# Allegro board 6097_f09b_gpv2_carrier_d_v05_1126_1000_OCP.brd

Outline 210 x 148 mm; copper layers: TOP, GND, IN1, GND1, VCC, VCC1, GND2, IN2, GND3, BOTTOM. Coordinates in mm from the lower left corner of the outline.
Outline path: 0,121.5 0,2 arc(0.59,0.59) 2,0 208,0 arc(209.41,0.59) 210,2 210,121.5 arc(209.41,122.91) 208,123.5 195.5,123.5 arc(194.09,124.09) 193.5,125.5 193.5,146 arc(192.91,147.41) 191.5,148 119.8,148 119.8,146.42 arc(119.38,146) 118.95,146.42 118.95,148 115.05,148 115.05,146.42 arc(114.63,146.01) 114.21,146.42 114.21,148 18.5,148 arc(17.09,147.41) 16.5,146 16.5,125.5 arc(15.91,124.09) 14.5,123.5 2,123.5 arc(0.59,122.91) 0,121.5 ; 27.08,20.8 arc(28.68,22.4) 30.28,20.8 30.28,19.2 arc(28.68,17.6) 27.08,19.2 27.08,20.8 ; 36.83,28.05 arc(38.43,29.65) 40.03,28.05 40.03,26.45 arc(38.43,24.85) 36.83,26.45 36.83,28.05 ; 51.08,20.8 arc(52.68,22.4) 54.28,20.8 54.28,19.2 arc(52.68,17.6) 51.08,19.2 51.08,20.8 ; 60.83,28.05 arc(62.43,29.65) 64.03,28.05 64.03,26.45 arc(62.43,24.85) 60.83,26.45 60.83,28.05 ; 75.08,20.8 arc(76.68,22.4) 78.28,20.8 78.28,19.2 arc(76.68,17.6) 75.08,19.2 75.08,20.8 ; 84.83,28.05 arc(86.43,29.65) 88.03,28.05 88.03,26.45 arc(86.43,24.85) 84.83,26.45 84.83,28.05 ; 99.08,20.8 arc(100.68,22.4) 102.28,20.8 102.28,19.2 arc(100.68,17.6) 99.08,19.2 99.08,20.8 ; 108.83,28.05 arc(110.43,29.65) 112.03,28.05 112.03,26.45 arc(110.43,24.85) 108.83,26.45 108.83,28.05 ; 112.49,146.88 arc(112.91,147.3) 113.33,146.88 113.33,146.22 arc(112.91,145.8) 112.49,146.22 112.49,146.88 ; 114.45,143.65 arc(114.78,143.98) 115.11,143.65 115.11,143.45 arc(114.78,143.12) 114.45,143.45 114.45,143.65 ; 118.9,143.65 arc(119.23,143.98) 119.56,143.65 119.56,143.45 arc(119.23,143.12) 118.9,143.45 118.9,143.65 ; 120.67,146.88 arc(121.09,147.3) 121.51,146.88 121.51,146.22 arc(121.09,145.8) 120.67,146.22 120.67,146.88 ; 123.08,20.8 arc(124.68,22.4) 126.28,20.8 126.28,19.2 arc(124.68,17.6) 123.08,19.2 123.08,20.8 ; 132.83,28.05 arc(134.43,29.65) 136.03,28.05 136.03,26.45 arc(134.43,24.85) 132.83,26.45 132.83,28.05 ; 147.08,20.8 arc(148.68,22.4) 150.28,20.8 150.28,19.2 arc(148.68,17.6) 147.08,19.2 147.08,20.8 ; 156.83,28.05 arc(158.43,29.65) 160.03,28.05 160.03,26.45 arc(158.43,24.85) 156.83,26.45 156.83,28.05

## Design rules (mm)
net group CLK_25M_MINIBMC_CLKIN_R: nets CLK_25M_MINIBMC_CLKIN CLK_25M_MINIBMC_CLKIN_R
net group CLK_100M_PESW_S3_DB1200_C_DN: nets CLK_100M_PESW_S3_DB1200_C_DN CLK_100M_PESW_S3_DB1200_DN
net group CLK_100M_PESW_S3_DB1200_C_DP: nets CLK_100M_PESW_S3_DB1200_C_DP CLK_100M_PESW_S3_DB1200_DP
net group CLKBUF_M2A_OE_N: nets CLKBUF_M2A_OE_N CLKBUF_M2A_OE_N_R
net group CLKBUF_M2B_OE_N: nets CLKBUF_M2B_OE_N CLKBUF_M2B_OE_N_R
net group CLKBUF_M2C_OE_N: nets CLKBUF_M2C_OE_N CLKBUF_M2C_OE_N_R
net group CLKBUF_M2D_OE_N: nets CLKBUF_M2D_OE_N CLKBUF_M2D_OE_N_R
net group CLKBUF_M2E_OE_N: nets CLKBUF_M2E_OE_N CLKBUF_M2E_OE_N_R
net group CLKBUF_M2F_OE_N: nets CLKBUF_M2F_OE_N CLKBUF_M2F_OE_N_R
net group CLKBUF_M2G_OE_N: nets CLKBUF_M2G_OE_N CLKBUF_M2G_OE_N_R
net group CLKBUF_M2H_OE_N: nets CLKBUF_M2H_OE_N CLKBUF_M2H_OE_N_R
net group CLKBUF_M2I_OE_N: nets CLKBUF_M2I_OE_N CLKBUF_M2I_OE_N_R
net group CLKBUF_M2J_OE_N: nets CLKBUF_M2J_OE_N CLKBUF_M2J_OE_N_R
net group CLKBUF_M2K_OE_N: nets CLKBUF_M2K_OE_N CLKBUF_M2K_OE_N_R
net group CLKBUF_M2L_OE_N: nets CLKBUF_M2L_OE_N CLKBUF_M2L_OE_N_R
net group COM_GP_TX: nets COM_GP_TX COM_GP_TX_R
net group FM_BIC_DEBUG_EN: nets FM_BIC_DEBUG_EN FM_BIC_DEBUG_EN_R
net group FM_BIC_M2A_EN: nets FM_BIC_M2A_EN FM_BIC_M2A_EN_R
net group FM_BIC_M2B_EN: nets FM_BIC_M2B_EN FM_BIC_M2B_EN_R
net group FM_BIC_M2C_EN: nets FM_BIC_M2C_EN FM_BIC_M2C_EN_R
net group FM_BIC_M2D_EN: nets FM_BIC_M2D_EN FM_BIC_M2D_EN_R
net group FM_BIC_M2E_EN: nets FM_BIC_M2E_EN FM_BIC_M2E_EN_R
net group FM_BIC_M2F_EN: nets FM_BIC_M2F_EN FM_BIC_M2F_EN_R
net group FM_BIC_M2G_EN: nets FM_BIC_M2G_EN FM_BIC_M2G_EN_R
net group FM_BIC_M2H_EN: nets FM_BIC_M2H_EN FM_BIC_M2H_EN_R
net group FM_BIC_M2I_EN: nets FM_BIC_M2I_EN FM_BIC_M2I_EN_R
net group FM_BIC_M2J_EN: nets FM_BIC_M2J_EN FM_BIC_M2J_EN_R
net group FM_BIC_M2K_EN: nets FM_BIC_M2K_EN FM_BIC_M2K_EN_R
net group FM_BIC_M2L_EN: nets FM_BIC_M2L_EN FM_BIC_M2L_EN_R
net group FM_CLKBUF_DB1200_EN_R: nets FM_CLKBUF_DB1200_EN FM_CLKBUF_DB1200_EN_R
net group FM_COM_EN_N: nets FM_COM_EN_N FM_COM_EN_N_R
net group FM_COM_SEL_0: nets FM_COM_SEL_0 FM_COM_SEL_0_R
net group FM_COM_SEL_1: nets FM_COM_SEL_1 FM_COM_SEL_1_R
net group FM_COM_SEL_2: nets FM_COM_SEL_2 FM_COM_SEL_2_R
net group FM_COM_SEL_3: nets FM_COM_SEL_3 FM_COM_SEL_3_R
net group FM_JTAG_EN_N: nets FM_JTAG_EN_N FM_JTAG_EN_N_R
net group FM_JTAG_SEL_0: nets FM_JTAG_SEL_0 FM_JTAG_SEL_0_R
net group FM_JTAG_SEL_1: nets FM_JTAG_SEL_1 FM_JTAG_SEL_1_R
net group FM_JTAG_SEL_2: nets FM_JTAG_SEL_2 FM_JTAG_SEL_2_R
net group FM_JTAG_SEL_3: nets FM_JTAG_SEL_3 FM_JTAG_SEL_3_R
net group FM_PLD_VCCIO_1_5_P1V8: nets FM_PLD_VCCIO_1_5_P1V8 FM_PLD_VCCIO_1_5_P1V8_R
net group FM_PLD_VCCIO_1_5_P3V3SB: nets FM_PLD_VCCIO_1_5_P3V3SB FM_PLD_VCCIO_1_5_P3V3SB_R
net group I2C_PESW_M2A_EN_LVC: nets I2C_PESW_M2A_EN_LVC I2C_PESW_M2A_EN_LVC_R
net group I2C_PESW_M2A_EN_R: nets I2C_PESW_M2A_EN I2C_PESW_M2A_EN_R
net group I2C_PESW_M2B_EN_LVC: nets I2C_PESW_M2B_EN_LVC I2C_PESW_M2B_EN_LVC_R
net group I2C_PESW_M2B_EN_R: nets I2C_PESW_M2B_EN I2C_PESW_M2B_EN_R
net group I2C_PESW_M2C_EN_LVC: nets I2C_PESW_M2C_EN_LVC I2C_PESW_M2C_EN_LVC_R
net group I2C_PESW_M2C_EN_R: nets I2C_PESW_M2C_EN I2C_PESW_M2C_EN_R
net group I2C_PESW_M2D_EN_LVC: nets I2C_PESW_M2D_EN_LVC I2C_PESW_M2D_EN_LVC_R
net group I2C_PESW_M2D_EN_R: nets I2C_PESW_M2D_EN I2C_PESW_M2D_EN_R
net group I2C_PESW_M2E_EN_LVC: nets I2C_PESW_M2E_EN_LVC I2C_PESW_M2E_EN_LVC_R
net group I2C_PESW_M2E_EN_R: nets I2C_PESW_M2E_EN I2C_PESW_M2E_EN_R
net group I2C_PESW_M2F_EN_LVC: nets I2C_PESW_M2F_EN_LVC I2C_PESW_M2F_EN_LVC_R
net group I2C_PESW_M2F_EN_R: nets I2C_PESW_M2F_EN I2C_PESW_M2F_EN_R
net group I2C_PESW_M2G_EN_LVC: nets I2C_PESW_M2G_EN_LVC I2C_PESW_M2G_EN_LVC_R
net group I2C_PESW_M2G_EN_R: nets I2C_PESW_M2G_EN I2C_PESW_M2G_EN_R
net group I2C_PESW_M2H_EN_LVC: nets I2C_PESW_M2H_EN_LVC I2C_PESW_M2H_EN_LVC_R
net group I2C_PESW_M2H_EN_R: nets I2C_PESW_M2H_EN I2C_PESW_M2H_EN_R
net group I2C_PESW_M2I_EN_LVC: nets I2C_PESW_M2I_EN_LVC I2C_PESW_M2I_EN_LVC_R
net group I2C_PESW_M2I_EN_R: nets I2C_PESW_M2I_EN I2C_PESW_M2I_EN_R
net group I2C_PESW_M2J_EN_LVC: nets I2C_PESW_M2J_EN_LVC I2C_PESW_M2J_EN_LVC_R
net group I2C_PESW_M2J_EN_R: nets I2C_PESW_M2J_EN I2C_PESW_M2J_EN_R
net group I2C_PESW_M2K_EN_LVC: nets I2C_PESW_M2K_EN_LVC I2C_PESW_M2K_EN_LVC_R
net group I2C_PESW_M2K_EN_R: nets I2C_PESW_M2K_EN I2C_PESW_M2K_EN_R
net group I2C_PESW_M2L_EN_LVC: nets I2C_PESW_M2L_EN_LVC I2C_PESW_M2L_EN_LVC_R
net group I2C_PESW_M2L_EN_R: nets I2C_PESW_M2L_EN I2C_PESW_M2L_EN_R
net group I2C_PESW_MULTI_CONFIG_ADD0: nets I2C_PESW_MULTI_CONFIG_ADD0 I2C_PESW_MULTI_CONFIG_ADD0_R
net group I2C_PESW_MULTI_CONFIG_ADD0_L: nets I2C_PESW_MULTI_CONFIG_ADD0_L I2C_PESW_MULTI_CONFIG_ADD0_L_R
net group I2C_PESW_MULTI_CONFIG_ADD1: nets I2C_PESW_MULTI_CONFIG_ADD1 I2C_PESW_MULTI_CONFIG_ADD1_R
net group I2C_PESW_MULTI_CONFIG_ADD1_L: nets I2C_PESW_MULTI_CONFIG_ADD1_L I2C_PESW_MULTI_CONFIG_ADD1_L_R
net group I2C_PESW_MULTI_CONFIG_ADD2: nets I2C_PESW_MULTI_CONFIG_ADD2 I2C_PESW_MULTI_CONFIG_ADD2_R
net group I2C_PESW_MULTI_CONFIG_ADD2_L: nets I2C_PESW_MULTI_CONFIG_ADD2_L I2C_PESW_MULTI_CONFIG_ADD2_L_R
net group I2C_PESW_MULTI_CONFIG_ADD3: nets I2C_PESW_MULTI_CONFIG_ADD3 I2C_PESW_MULTI_CONFIG_ADD3_R
net group I2C_PESW_MULTI_CONFIG_ADD3_L: nets I2C_PESW_MULTI_CONFIG_ADD3_L I2C_PESW_MULTI_CONFIG_ADD3_L_R
net group I2C_PESW_MULTI_CONFIG_ADD4: nets I2C_PESW_MULTI_CONFIG_ADD4 I2C_PESW_MULTI_CONFIG_ADD4_R
net group I2C_PESW_MULTI_CONFIG_ADD4_L: nets I2C_PESW_MULTI_CONFIG_ADD4_L I2C_PESW_MULTI_CONFIG_ADD4_L_R
net group JTAG_BIC_M2_TCK: nets JTAG_BIC_M2_TCK JTAG_BIC_M2_TCK_R
net group JTAG_BIC_M2_TDI: nets JTAG_BIC_M2_TDI JTAG_BIC_M2_TDI_R
net group JTAG_BIC_M2_TDO: nets JTAG_BIC_M2_TDO JTAG_BIC_M2_TDO_R
net group JTAG_BIC_M2_TMS: nets JTAG_BIC_M2_TMS JTAG_BIC_M2_TMS_R
net group JTAG_CPLD_M2A_TCK: nets JTAG_CPLD_M2A_TCK JTAG_CPLD_M2A_TCK_R
net group JTAG_CPLD_M2A_TDI: nets JTAG_CPLD_M2A_TDI JTAG_CPLD_M2A_TDI_R
net group JTAG_CPLD_M2A_TMS: nets JTAG_CPLD_M2A_TMS JTAG_CPLD_M2A_TMS_R
net group JTAG_CPLD_M2A_TRST: nets JTAG_CPLD_M2A_TRST JTAG_CPLD_M2A_TRST_R
net group JTAG_CPLD_M2B_TCK: nets JTAG_CPLD_M2B_TCK JTAG_CPLD_M2B_TCK_R
net group JTAG_CPLD_M2B_TDI: nets JTAG_CPLD_M2B_TDI JTAG_CPLD_M2B_TDI_R
net group JTAG_CPLD_M2B_TMS: nets JTAG_CPLD_M2B_TMS JTAG_CPLD_M2B_TMS_R
net group JTAG_CPLD_M2B_TRST: nets JTAG_CPLD_M2B_TRST JTAG_CPLD_M2B_TRST_R
net group JTAG_CPLD_M2C_TCK: nets JTAG_CPLD_M2C_TCK JTAG_CPLD_M2C_TCK_R
net group JTAG_CPLD_M2C_TDI: nets JTAG_CPLD_M2C_TDI JTAG_CPLD_M2C_TDI_R
net group JTAG_CPLD_M2C_TMS: nets JTAG_CPLD_M2C_TMS JTAG_CPLD_M2C_TMS_R
net group JTAG_CPLD_M2C_TRST: nets JTAG_CPLD_M2C_TRST JTAG_CPLD_M2C_TRST_R
net group JTAG_CPLD_M2D_TCK: nets JTAG_CPLD_M2D_TCK JTAG_CPLD_M2D_TCK_R
net group JTAG_CPLD_M2D_TDI: nets JTAG_CPLD_M2D_TDI JTAG_CPLD_M2D_TDI_R
net group JTAG_CPLD_M2D_TMS: nets JTAG_CPLD_M2D_TMS JTAG_CPLD_M2D_TMS_R
net group JTAG_CPLD_M2D_TRST: nets JTAG_CPLD_M2D_TRST JTAG_CPLD_M2D_TRST_R
net group JTAG_CPLD_M2E_TCK: nets JTAG_CPLD_M2E_TCK JTAG_CPLD_M2E_TCK_R
net group JTAG_CPLD_M2E_TDI: nets JTAG_CPLD_M2E_TDI JTAG_CPLD_M2E_TDI_R
net group JTAG_CPLD_M2E_TMS: nets JTAG_CPLD_M2E_TMS JTAG_CPLD_M2E_TMS_R
net group JTAG_CPLD_M2E_TRST: nets JTAG_CPLD_M2E_TRST JTAG_CPLD_M2E_TRST_R
net group JTAG_CPLD_M2F_TCK: nets JTAG_CPLD_M2F_TCK JTAG_CPLD_M2F_TCK_R
net group JTAG_CPLD_M2F_TDI: nets JTAG_CPLD_M2F_TDI JTAG_CPLD_M2F_TDI_R
net group JTAG_CPLD_M2F_TMS: nets JTAG_CPLD_M2F_TMS JTAG_CPLD_M2F_TMS_R
net group JTAG_CPLD_M2F_TRST: nets JTAG_CPLD_M2F_TRST JTAG_CPLD_M2F_TRST_R
net group JTAG_CPLD_M2G_TCK: nets JTAG_CPLD_M2G_TCK JTAG_CPLD_M2G_TCK_R
net group JTAG_CPLD_M2G_TDI: nets JTAG_CPLD_M2G_TDI JTAG_CPLD_M2G_TDI_R
net group JTAG_CPLD_M2G_TMS: nets JTAG_CPLD_M2G_TMS JTAG_CPLD_M2G_TMS_R
net group JTAG_CPLD_M2G_TRST: nets JTAG_CPLD_M2G_TRST JTAG_CPLD_M2G_TRST_R
net group JTAG_CPLD_M2H_TCK: nets JTAG_CPLD_M2H_TCK JTAG_CPLD_M2H_TCK_R
net group JTAG_CPLD_M2H_TDI: nets JTAG_CPLD_M2H_TDI JTAG_CPLD_M2H_TDI_R
net group JTAG_CPLD_M2H_TMS: nets JTAG_CPLD_M2H_TMS JTAG_CPLD_M2H_TMS_R
net group JTAG_CPLD_M2H_TRST: nets JTAG_CPLD_M2H_TRST JTAG_CPLD_M2H_TRST_R
net group JTAG_CPLD_M2I_TCK: nets JTAG_CPLD_M2I_TCK JTAG_CPLD_M2I_TCK_R
net group JTAG_CPLD_M2I_TDI: nets JTAG_CPLD_M2I_TDI JTAG_CPLD_M2I_TDI_R
net group JTAG_CPLD_M2I_TMS: nets JTAG_CPLD_M2I_TMS JTAG_CPLD_M2I_TMS_R
net group JTAG_CPLD_M2I_TRST: nets JTAG_CPLD_M2I_TRST JTAG_CPLD_M2I_TRST_R
net group JTAG_CPLD_M2J_TCK: nets JTAG_CPLD_M2J_TCK JTAG_CPLD_M2J_TCK_R
net group JTAG_CPLD_M2J_TDI: nets JTAG_CPLD_M2J_TDI JTAG_CPLD_M2J_TDI_R
net group JTAG_CPLD_M2J_TMS: nets JTAG_CPLD_M2J_TMS JTAG_CPLD_M2J_TMS_R
net group JTAG_CPLD_M2J_TRST: nets JTAG_CPLD_M2J_TRST JTAG_CPLD_M2J_TRST_R
net group JTAG_CPLD_M2K_TCK: nets JTAG_CPLD_M2K_TCK JTAG_CPLD_M2K_TCK_R
net group JTAG_CPLD_M2K_TDI: nets JTAG_CPLD_M2K_TDI JTAG_CPLD_M2K_TDI_R
net group JTAG_CPLD_M2K_TMS: nets JTAG_CPLD_M2K_TMS JTAG_CPLD_M2K_TMS_R
net group JTAG_CPLD_M2K_TRST: nets JTAG_CPLD_M2K_TRST JTAG_CPLD_M2K_TRST_R
net group JTAG_CPLD_M2L_TCK: nets JTAG_CPLD_M2L_TCK JTAG_CPLD_M2L_TCK_R
net group JTAG_CPLD_M2L_TDI: nets JTAG_CPLD_M2L_TDI JTAG_CPLD_M2L_TDI_R
net group JTAG_CPLD_M2L_TMS: nets JTAG_CPLD_M2L_TMS JTAG_CPLD_M2L_TMS_R
net group JTAG_CPLD_M2L_TRST: nets JTAG_CPLD_M2L_TRST JTAG_CPLD_M2L_TRST_R
net group JTAG_CPLD_TCK: nets JTAG_CPLD_TCK JTAG_CPLD_TCK_R
net group JTAG_CPLD_TDI: nets JTAG_CPLD_TDI JTAG_CPLD_TDI_R
net group JTAG_CPLD_TDO: nets JTAG_CPLD_TDO JTAG_CPLD_TDO_R
net group JTAG_CPLD_TMS: nets JTAG_CPLD_TMS JTAG_CPLD_TMS_R
net group JTAG_PESW_TDI: nets JTAG_PESE_TDI_R JTAG_PESW_TDI
net group JTAG_PESW_TDO: nets JTAG_PESW_TDO JTAG_PESW_TDO_R
net group JTAG_TI_TCK: nets JTAG_TI_TCK JTAG_TI_TCK_R
net group JTAG_TI_TDI: nets JTAG_TI_TDI JTAG_TI_TDI_R
net group JTAG_TI_TMS: nets JTAG_TI_TMS JTAG_TI_TMS_R
net group LATCH_DETECT: nets LATCH_DETECT LATCH_DETECT_R
net group P0V9_BOOTC: nets P0V9_BOOTC SW_P0V9_1
net group P0V9_VOSNS+: nets P0V9_VOSNS+ P0V92_SENSE+
net group P3E_PESW_M2E_TX0_C_DN: nets P3E_PESW_M2E_TX0_C_DN P3E_PESW_M2E_TX0_DN
net group P3E_PESW_M2E_TX0_C_DP: nets P3E_PESW_M2E_TX0_C_DP P3E_PESW_M2E_TX0_DP
net group P3E_PESW_M2E_TX1_C_DN: nets P3E_PESW_M2E_TX1_C_DN P3E_PESW_M2E_TX1_DN
net group P3E_PESW_M2E_TX1_C_DP: nets P3E_PESW_M2E_TX1_C_DP P3E_PESW_M2E_TX1_DP
net group P3E_PESW_M2E_TX2_C_DN: nets P3E_PESW_M2E_TX2_C_DN P3E_PESW_M2E_TX2_DN
net group P3E_PESW_M2E_TX2_C_DP: nets P3E_PESW_M2E_TX2_C_DP P3E_PESW_M2E_TX2_DP
net group P3E_PESW_M2E_TX3_C_DN: nets P3E_PESW_M2E_TX3_C_DN P3E_PESW_M2E_TX3_DN
net group P3E_PESW_M2E_TX3_C_DP: nets P3E_PESW_M2E_TX3_C_DP P3E_PESW_M2E_TX3_DP
net group P3E_PESW_M2F_TX0_C_DN: nets P3E_PESW_M2F_TX0_C_DN P3E_PESW_M2F_TX0_DN
net group P3E_PESW_M2F_TX0_C_DP: nets P3E_PESW_M2F_TX0_C_DP P3E_PESW_M2F_TX0_DP
net group P3E_PESW_M2F_TX1_C_DN: nets P3E_PESW_M2F_TX1_C_DN P3E_PESW_M2F_TX1_DN
net group P3E_PESW_M2F_TX1_C_DP: nets P3E_PESW_M2F_TX1_C_DP P3E_PESW_M2F_TX1_DP
net group P3E_PESW_M2F_TX2_C_DN: nets P3E_PESW_M2F_TX2_C_DN P3E_PESW_M2F_TX2_DN
net group P3E_PESW_M2F_TX2_C_DP: nets P3E_PESW_M2F_TX2_C_DP P3E_PESW_M2F_TX2_DP
net group P3E_PESW_M2F_TX3_C_DN: nets P3E_PESW_M2F_TX3_C_DN P3E_PESW_M2F_TX3_DN
net group P3E_PESW_M2F_TX3_C_DP: nets P3E_PESW_M2F_TX3_C_DP P3E_PESW_M2F_TX3_DP
net group P3E_PESW_M2G_TX0_C_DN: nets P3E_PESW_M2G_TX0_C_DN P3E_PESW_M2G_TX0_DN
net group P3E_PESW_M2G_TX0_C_DP: nets P3E_PESW_M2G_TX0_C_DP P3E_PESW_M2G_TX0_DP
net group P3E_PESW_M2G_TX1_C_DN: nets P3E_PESW_M2G_TX1_C_DN P3E_PESW_M2G_TX1_DN
net group P3E_PESW_M2G_TX1_C_DP: nets P3E_PESW_M2G_TX1_C_DP P3E_PESW_M2G_TX1_DP
net group P3E_PESW_M2G_TX2_C_DN: nets P3E_PESW_M2G_TX2_C_DN P3E_PESW_M2G_TX2_DN
net group P3E_PESW_M2G_TX2_C_DP: nets P3E_PESW_M2G_TX2_C_DP P3E_PESW_M2G_TX2_DP
net group P3E_PESW_M2G_TX3_C_DN: nets P3E_PESW_M2G_TX3_C_DN P3E_PESW_M2G_TX3_DN
net group P3E_PESW_M2G_TX3_C_DP: nets P3E_PESW_M2G_TX3_C_DP P3E_PESW_M2G_TX3_DP
net group P3E_PESW_M2H_TX0_C_DN: nets P3E_PESW_M2H_TX0_C_DN P3E_PESW_M2H_TX0_DN
net group P3E_PESW_M2H_TX0_C_DP: nets P3E_PESW_M2H_TX0_C_DP P3E_PESW_M2H_TX0_DP
net group P3E_PESW_M2H_TX1_C_DN: nets P3E_PESW_M2H_TX1_C_DN P3E_PESW_M2H_TX1_DN
net group P3E_PESW_M2H_TX1_C_DP: nets P3E_PESW_M2H_TX1_C_DP P3E_PESW_M2H_TX1_DP
net group P3E_PESW_M2H_TX2_C_DN: nets P3E_PESW_M2H_TX2_C_DN P3E_PESW_M2H_TX2_DN
net group P3E_PESW_M2H_TX2_C_DP: nets P3E_PESW_M2H_TX2_C_DP P3E_PESW_M2H_TX2_DP
net group P3E_PESW_M2H_TX3_C_DN: nets P3E_PESW_M2H_TX3_C_DN P3E_PESW_M2H_TX3_DN
net group P3E_PESW_M2H_TX3_C_DP: nets P3E_PESW_M2H_TX3_C_DP P3E_PESW_M2H_TX3_DP
net group P3E_PESW_M2K_TX0_C_DN: nets P3E_PESW_M2K_TX0_C_DN P3E_PESW_M2K_TX0_DN
net group P3E_PESW_M2K_TX0_C_DP: nets P3E_PESW_M2K_TX0_C_DP P3E_PESW_M2K_TX0_DP
net group P3E_PESW_M2K_TX1_C_DN: nets P3E_PESW_M2K_TX1_C_DN P3E_PESW_M2K_TX1_DN
net group P3E_PESW_M2K_TX1_C_DP: nets P3E_PESW_M2K_TX1_C_DP P3E_PESW_M2K_TX1_DP
net group P3E_PESW_M2K_TX2_C_DN: nets P3E_PESW_M2K_TX2_C_DN P3E_PESW_M2K_TX2_DN
net group P3E_PESW_M2K_TX2_C_DP: nets P3E_PESW_M2K_TX2_C_DP P3E_PESW_M2K_TX2_DP
net group P3E_PESW_M2K_TX3_C_DN: nets P3E_PESW_M2K_TX3_C_DN P3E_PESW_M2K_TX3_DN
net group P3E_PESW_M2K_TX3_C_DP: nets P3E_PESW_M2K_TX3_C_DP P3E_PESW_M2K_TX3_DP
net group P3E_PESW_M2L_TX0_C_DN: nets P3E_PESW_M2L_TX0_C_DN P3E_PESW_M2L_TX0_DN
net group P3E_PESW_M2L_TX0_C_DP: nets P3E_PESW_M2L_TX0_C_DP P3E_PESW_M2L_TX0_DP
net group P3E_PESW_M2L_TX1_C_DN: nets P3E_PESW_M2L_TX1_C_DN P3E_PESW_M2L_TX1_DN
net group P3E_PESW_M2L_TX1_C_DP: nets P3E_PESW_M2L_TX1_C_DP P3E_PESW_M2L_TX1_DP
net group P3E_PESW_M2L_TX2_C_DN: nets P3E_PESW_M2L_TX2_C_DN P3E_PESW_M2L_TX2_DN
net group P3E_PESW_M2L_TX2_C_DP: nets P3E_PESW_M2L_TX2_C_DP P3E_PESW_M2L_TX2_DP
net group P3E_PESW_M2L_TX3_C_DN: nets P3E_PESW_M2L_TX3_C_DN P3E_PESW_M2L_TX3_DN
net group P3E_PESW_M2L_TX3_C_DP: nets P3E_PESW_M2L_TX3_C_DP P3E_PESW_M2L_TX3_DP
net group P3V3_BOOTC_1: nets P3V3_BOOTC_1 SW_P3V3_STBY_1
net group P3V3_BOOTC_2: nets P3V3_BOOTC_2 SW_P3V3_STBY_2
net group P3V3_M2A_EN: nets P3V3_M2A_EN P3V3_M2A_EN_R
net group P3V3_M2B_EN: nets P3V3_M2B_EN P3V3_M2B_EN_R
net group P3V3_M2C_EN: nets P3V3_M2C_EN P3V3_M2C_EN_R
net group P3V3_M2D_EN: nets P3V3_M2D_EN P3V3_M2D_EN_R
net group P3V3_M2E_EN: nets P3V3_M2E_EN P3V3_M2E_EN_R
net group P3V3_M2F_EN: nets P3V3_M2F_EN P3V3_M2F_EN_R
net group P3V3_M2G_EN: nets P3V3_M2G_EN P3V3_M2G_EN_R
net group P3V3_M2H_EN: nets P3V3_M2H_EN P3V3_M2H_EN_R
net group P3V3_M2I_EN: nets P3V3_M2I_EN P3V3_M2I_EN_R
net group P3V3_M2J_EN: nets P3V3_M2J_EN P3V3_M2J_EN_R
net group P3V3_M2K_EN: nets P3V3_M2K_EN P3V3_M2K_EN_R
net group P3V3_M2L_EN: nets P3V3_M2L_EN P3V3_M2L_EN_R
net group P3V3_OR_M2A_EN: nets P3V3_OR_M2A_EN P3V3_OR_M2A_EN_R
net group P3V3_OR_M2B_EN: nets P3V3_OR_M2B_EN P3V3_OR_M2B_EN_R
net group P3V3_OR_M2C_EN: nets P3V3_OR_M2C_EN P3V3_OR_M2C_EN_R
net group P3V3_OR_M2D_EN: nets P3V3_OR_M2D_EN P3V3_OR_M2D_EN_R
net group P3V3_OR_M2E_EN: nets P3V3_OR_M2E_EN P3V3_OR_M2E_EN_R
net group P3V3_OR_M2F_EN: nets P3V3_OR_M2F_EN P3V3_OR_M2F_EN_R
net group P3V3_OR_M2G_EN: nets P3V3_OR_M2G_EN P3V3_OR_M2G_EN_R
net group P3V3_OR_M2H_EN: nets P3V3_OR_M2H_EN P3V3_OR_M2H_EN_R
net group P3V3_OR_M2I_EN: nets P3V3_OR_M2I_EN P3V3_OR_M2I_EN_R
net group P3V3_OR_M2J_EN: nets P3V3_OR_M2J_EN P3V3_OR_M2J_EN_R
net group P3V3_OR_M2K_EN: nets P3V3_OR_M2K_EN P3V3_OR_M2K_EN_R
net group P3V3_OR_M2L_EN: nets P3V3_OR_M2L_EN P3V3_OR_M2L_EN_R
net group PWRGD_P3V3_M2A: nets PWRGD_P3V3_M2A PWRGD_P3V3_M2A_R
net group PWRGD_P3V3_M2B: nets PWRGD_P3V3_M2B PWRGD_P3V3_M2B_R
net group PWRGD_P3V3_M2C: nets PWRGD_P3V3_M2C PWRGD_P3V3_M2C_R
net group PWRGD_P3V3_M2D: nets PWRGD_P3V3_M2D PWRGD_P3V3_M2D_R
net group PWRGD_P3V3_M2E: nets PWRGD_P3V3_M2E PWRGD_P3V3_M2E_R
net group PWRGD_P3V3_M2F: nets PWRGD_P3V3_M2F PWRGD_P3V3_M2F_R
net group PWRGD_P3V3_M2G: nets PWRGD_P3V3_M2G PWRGD_P3V3_M2G_R
net group PWRGD_P3V3_M2H: nets PWRGD_P3V3_M2H PWRGD_P3V3_M2H_R
net group PWRGD_P3V3_M2I: nets PWRGD_P3V3_M2I PWRGD_P3V3_M2I_R
net group PWRGD_P3V3_M2J: nets PWRGD_P3V3_M2J PWRGD_P3V3_M2J_R
net group PWRGD_P3V3_M2K: nets PWRGD_P3V3_M2K PWRGD_P3V3_M2K_R
net group PWRGD_P3V3_M2L: nets PWRGD_P3V3_M2L PWRGD_P3V3_M2L_R
net group RST_I2C_MUX1_N: nets RST_I2C_MUX1_N RST_I2C_MUX1_N_R
net group RST_I2C_MUX2_N: nets RST_I2C_MUX2_N RST_I2C_MUX2_N_R
net group RST_I2C_MUX3_N: nets RST_I2C_MUX3_N RST_I2C_MUX3_N_R
net group RST_I2C_MUX4_N: nets RST_I2C_MUX4_N RST_I2C_MUX4_N_R
net group RST_I2C_MUX5_N: nets RST_I2C_MUX5_N RST_I2C_MUX5_N_R
net group RST_I2C_MUX6_N: nets RST_I2C_MUX6_N RST_I2C_MUX6_N_R
net group RST_I2C_MUX7_N: nets RST_I2C_MUX7_N RST_I2C_MUX7_N_R
net group RST_PE_PESW_RSTB_N: nets RST_PE_PESW_RSTB_N RST_PE_PESW_RSTB_N_R
net group RST_PE_SLOT1_1_RESET_N: nets RST_PE_SLOT1_1_RESET_N RST_PE_SLOT1_1_RESET_N_R
net group RST_PESW_M2A_LVC_N: nets RST_PESW_M2A_LVC_N RST_PESW_M2A_LVC_N_R
net group RST_PESW_M2A_N: nets RST_PESW_M2A_N RST_PESW_M2A_N_R
net group RST_PESW_M2B_LVC_N: nets RST_PESW_M2B_LVC_N RST_PESW_M2B_LVC_N_R
net group RST_PESW_M2B_N: nets RST_PESW_M2B_N RST_PESW_M2B_N_R
net group RST_PESW_M2C_LVC_N: nets RST_PESW_M2C_LVC_N RST_PESW_M2C_LVC_N_R
net group RST_PESW_M2C_N: nets RST_PESW_M2C_N RST_PESW_M2C_N_R
net group RST_PESW_M2D_LVC_N: nets RST_PESW_M2D_LVC_N RST_PESW_M2D_LVC_N_R
net group RST_PESW_M2D_N: nets RST_PESW_M2D_N RST_PESW_M2D_N_R
net group RST_PESW_M2E_LVC_N: nets RST_PESW_M2E_LVC_N RST_PESW_M2E_LVC_N_R
net group RST_PESW_M2E_N: nets RST_PESW_M2E_N RST_PESW_M2E_N_R
net group RST_PESW_M2F_LVC_N: nets RST_PESW_M2F_LVC_N RST_PESW_M2F_LVC_N_R
net group RST_PESW_M2F_N: nets RST_PESW_M2F_N RST_PESW_M2F_N_R
net group RST_PESW_M2G_LVC_N: nets RST_PESW_M2G_LVC_N RST_PESW_M2G_LVC_N_R
net group RST_PESW_M2G_N: nets RST_PESW_M2G_N RST_PESW_M2G_N_R
net group RST_PESW_M2H_LVC_N: nets RST_PESW_M2H_LVC_N RST_PESW_M2H_LVC_N_R
net group RST_PESW_M2H_N: nets RST_PESW_M2H_N RST_PESW_M2H_N_R
net group RST_PESW_M2I_LVC_N: nets RST_PESW_M2I_LVC_N RST_PESW_M2I_LVC_N_R
net group RST_PESW_M2I_N: nets RST_PESW_M2I_N RST_PESW_M2I_N_R
net group RST_PESW_M2J_LVC_N: nets RST_PESW_M2J_LVC_N RST_PESW_M2J_LVC_N_R
net group RST_PESW_M2J_N: nets RST_PESW_M2J_N RST_PESW_M2J_N_R
net group RST_PESW_M2K_LVC_N: nets RST_PESW_M2K_LVC_N RST_PESW_M2K_LVC_N_R
net group RST_PESW_M2K_N: nets RST_PESW_M2K_N RST_PESW_M2K_N_R
net group RST_PESW_M2L_LVC_N: nets RST_PESW_M2L_LVC_N RST_PESW_M2L_LVC_N_R
net group RST_PESW_M2L_N: nets RST_PESW_M2L_N RST_PESW_M2L_N_R
net group SMB_BIC_3V3SB_READY_N: nets SMB_BIC_3V3SB_READY_N SMB_BIC_3V3SB_READY_N_R
net group SMB_INA230_ALERT_N: nets SMB_INA230_ALERT_N SMB_INA230_ALERT_N_R
net group SMB_M2A_ALERT_LVC_N: nets SMB_M2A_ALERT_LVC_N SMB_M2A_ALERT_LVC_N_R
net group SMB_M2A_INA231_ALRT_N: nets SMB_M2A_INA231_ALRT_N SMB_M2A_INA231_ALRT_N_R
net group SMB_M2B_ALERT_LVC_N: nets SMB_M2B_ALERT_LVC_N SMB_M2B_ALERT_LVC_N_R
net group SMB_M2B_INA231_ALRT_N: nets SMB_M2B_INA231_ALRT_N SMB_M2B_INA231_ALRT_N_R
net group SMB_M2C_ALERT_LVC_N: nets SMB_M2C_ALERT_LVC_N SMB_M2C_ALERT_LVC_N_R
net group SMB_M2C_INA231_ALRT_N: nets SMB_M2C_INA231_ALRT_N SMB_M2C_INA231_ALRT_N_R
net group SMB_M2D_ALERT_LVC_N: nets SMB_M2D_ALERT_LVC_N SMB_M2D_ALERT_LVC_N_R
net group SMB_M2D_INA231_ALRT_N: nets SMB_M2D_INA231_ALRT_N SMB_M2D_INA231_ALRT_N_R
net group SMB_M2E_ALERT_LVC_N: nets SMB_M2E_ALERT_LVC_N SMB_M2E_ALERT_LVC_N_R
net group SMB_M2E_INA231_ALRT_N: nets SMB_M2E_INA231_ALRT_N SMB_M2E_INA231_ALRT_N_R
net group SMB_M2F_ALERT_LVC_N: nets SMB_M2F_ALERT_LVC_N SMB_M2F_ALERT_LVC_N_R
net group SMB_M2F_INA231_ALRT_N: nets SMB_M2F_INA231_ALRT_N SMB_M2F_INA231_ALRT_N_R
net group SMB_M2G_ALERT_LVC_N: nets SMB_M2G_ALERT_LVC_N SMB_M2G_ALERT_LVC_N_R
net group SMB_M2G_INA231_ALRT_N: nets SMB_M2G_INA231_ALRT_N SMB_M2G_INA231_ALRT_N_R
net group SMB_M2H_ALERT_LVC_N: nets SMB_M2H_ALERT_LVC_N SMB_M2H_ALERT_LVC_N_R
net group SMB_M2H_INA231_ALRT_N: nets SMB_M2H_INA231_ALRT_N SMB_M2H_INA231_ALRT_N_R
net group SMB_M2I_ALERT_LVC_N: nets SMB_M2I_ALERT_LVC_N SMB_M2I_ALERT_LVC_N_R
net group SMB_M2I_INA231_ALRT_N: nets SMB_M2I_INA231_ALRT_N SMB_M2I_INA231_ALRT_N_R
net group SMB_M2J_ALERT_LVC_N: nets SMB_M2J_ALERT_LVC_N SMB_M2J_ALERT_LVC_N_R
net group SMB_M2J_INA231_ALRT_N: nets SMB_M2J_INA231_ALRT_N SMB_M2J_INA231_ALRT_N_R
net group SMB_M2K_ALERT_LVC_N: nets SMB_M2K_ALERT_LVC_N SMB_M2K_ALERT_LVC_N_R
net group SMB_M2K_INA231_ALRT_N: nets SMB_M2K_INA231_ALRT_N SMB_M2K_INA231_ALRT_N_R
net group SMB_M2L_ALERT_LVC_N: nets SMB_M2L_ALERT_LVC_N SMB_M2L_ALERT_LVC_N_R
net group SMB_M2L_INA231_ALRT_N: nets SMB_M2L_INA231_ALRT_N SMB_M2L_INA231_ALRT_N_R
net group SMB_MUX_VR_CLK: nets SMB_MUX_VR_CLK SMB_MUX_VR_CLK_R
net group SMB_MUX_VR_DAT: nets SMB_MUX_VR_DAT SMB_MUX_VR_DAT_R
net group SMB_SENSOR_ZL30281_CLK: nets SMB_SENSOR_ZL30281_CLK SMB_SENSOR_ZL30281_CLK_R1
net group SMB_SENSOR_ZL30281_DAT: nets SMB_SENSOR_ZL30281_DAT SMB_SENSOR_ZL30281_DAT_R1
net group SPI_PESW_FLASH_DAT_3_R2: nets SPI_PESW_FLASH_DAT_3 SPI_PESW_FLASH_DAT_3_R1
net group TMP_ALERT_U7_N: nets TMP_ALERT_U7_N TMP_ALERT_U7_N_R
net group TMP_ALERT_U8_N: nets TMP_ALERT_U8_N TMP_ALERT_U8_N_R
net group UART_BIC_RXD: nets UART_BIC_RXD UART_BIC_RXD_R
net group UART_BIC_RXD_REMOTE: nets UART_BIC_RXD_REMOTE UART_BIC_RXD_REMOTE_R
net group UART_BIC_TXD_REMOTE: nets UART_BIC_TXD_REMOTE UART_BIC_TXD_REMOTE_R
net group XTAL_25M_ZL30281_XB_R: nets XTAL_25M_ZL30281_XB XTAL_25M_ZL30281_XB_R
net group CLK_100M_DB1200_M2A_DN: nets CLK_100M_DB1200_M2A_DN
net group CLK_100M_DB1200_M2A_DP: nets CLK_100M_DB1200_M2A_R_DP
net group CLK_100M_DB1200_M2B_DN: nets CLK_100M_DB1200_M2B_R_DN
net group CLK_100M_DB1200_M2B_DP: nets CLK_100M_DB1200_M2B_R_DP
net group CLK_100M_DB1200_M2C_DN: nets CLK_100M_DB1200_M2C_R_DN
net group CLK_100M_DB1200_M2C_DP: nets CLK_100M_DB1200_M2C_R_DP
net group CLK_100M_DB1200_M2D_DN: nets CLK_100M_DB1200_M2D_R_DN
net group CLK_100M_DB1200_M2D_DP: nets CLK_100M_DB1200_M2D_R_DP
net group CLK_100M_DB1200_M2E_DN: nets CLK_100M_DB1200_M2E_R_DN
net group CLK_100M_DB1200_M2E_DP: nets CLK_100M_DB1200_M2E_R_DP
net group CLK_100M_DB1200_M2F_DN: nets CLK_100M_DB1200_M2F_R_DN
net group CLK_100M_DB1200_M2F_DP: nets CLK_100M_DB1200_M2F_R_DP
net group CLK_100M_DB1200_M2G_DN: nets CLK_100M_DB1200_M2G_R_DN
net group CLK_100M_DB1200_M2G_DP: nets CLK_100M_DB1200_M2G_R_DP
net group CLK_100M_DB1200_M2H_DN: nets CLK_100M_DB1200_M2H_R_DN
net group CLK_100M_DB1200_M2H_DP: nets CLK_100M_DB1200_M2H_R_DP
net group CLK_100M_DB1200_M2I_DN: nets CLK_100M_DB1200_M2I_R_DN
net group CLK_100M_DB1200_M2I_DP: nets CLK_100M_DB1200_M2I_R_DP
net group CLK_100M_DB1200_M2J_DN: nets CLK_100M_DB1200_M2J_R_DN
net group CLK_100M_DB1200_M2J_DP: nets CLK_100M_DB1200_M2J_R_DP
net group CLK_100M_DB1200_M2K_DN: nets CLK_100M_DB1200_M2K_R_DN
net group CLK_100M_DB1200_M2K_DP: nets CLK_100M_DB1200_M2K_R_DP
net group CLK_100M_DB1200_M2L_DN: nets CLK_100M_DB1200_M2L_R_DN
net group CLK_100M_DB1200_M2L_DP: nets CLK_100M_DB1200_M2L_R_DP
net group CLK_100M_PESW_H2_R_C_DN: nets CLK_100M_PESW_H2_R_C_DN
net group CLK_100M_PESW_H2_R_C_DP: nets CLK_100M_PESW_H2_R_C_DP
net group CLK_XTAL: nets XTAL_25M_ZL30281_XA
net group COM_CPLD_M2A_RX: nets COM_CPLD_M2A_RX
net group COM_CPLD_M2A_TX: nets COM_CPLD_M2A_TX
net group COM_CPLD_M2B_RX: nets COM_CPLD_M2B_RX
net group COM_CPLD_M2B_TX: nets COM_CPLD_M2B_TX
net group COM_CPLD_M2C_RX: nets COM_CPLD_M2C_RX
net group COM_CPLD_M2C_TX: nets COM_CPLD_M2C_TX
net group COM_CPLD_M2D_RX: nets COM_CPLD_M2D_RX
net group COM_CPLD_M2D_TX: nets COM_CPLD_M2D_TX
net group COM_CPLD_M2E_RX: nets COM_CPLD_M2E_RX
net group COM_CPLD_M2E_TX: nets COM_CPLD_M2E_TX
net group COM_CPLD_M2F_RX: nets COM_CPLD_M2F_RX
net group COM_CPLD_M2F_TX: nets COM_CPLD_M2F_TX
net group COM_CPLD_M2G_RX: nets COM_CPLD_M2G_RX
net group COM_CPLD_M2G_TX: nets COM_CPLD_M2G_TX
net group COM_CPLD_M2H_RX: nets COM_CPLD_M2H_RX
net group COM_CPLD_M2H_TX: nets COM_CPLD_M2H_TX
net group COM_CPLD_M2I_RX: nets COM_CPLD_M2I_RX
net group COM_CPLD_M2I_TX: nets COM_CPLD_M2I_TX
net group COM_CPLD_M2J_RX: nets COM_CPLD_M2J_RX
net group COM_CPLD_M2J_TX: nets COM_CPLD_M2J_TX
net group COM_CPLD_M2K_RX: nets COM_CPLD_M2K_RX
net group COM_CPLD_M2K_TX: nets COM_CPLD_M2K_TX
net group COM_CPLD_M2L_RX: nets COM_CPLD_M2L_RX
net group COM_CPLD_M2L_TX: nets COM_CPLD_M2L_TX
net group DEITA_L: nets DELTA_L_85_5IN_BOT_DN DELTA_L_85_5IN_BOT_DP DELTA_L_85_5IN_IN1_DN DELTA_L_85_5IN_IN1_DP DELTA_L_85_5IN_IN2_DN DELTA_L_85_5IN_IN2_DP DELTA_L_85_5IN_TOP_DN DELTA_L_85_5IN_TOP_DP DELTA_L_85_10IN_BOT_DN DELTA_L_85_10IN_BOT_DP DELTA_L_85_10IN_IN1_DN DELTA_L_85_10IN_IN1_DP DELTA_L_85_10IN_IN2_DN DELTA_L_85_10IN_IN2_DP DELTA_L_85_10IN_TOP_DN DELTA_L_85_10IN_TOP_DP
net group JTAG: nets JTAG_PESW_TRSTB
net group JTAG_BIC_M2_TRST: nets JTAG_BIC_M2_TRST_R
net group JTAG_TI_TDO: nets JTAG_TI_TDO
net group LED_P12V: nets LED_P12V P3V3_STBY_CTRL P12V_STBY
net group M2A_LED: nets M2A_LED P3V3_M2A_L PU_M2A_CLKREQ_N
net group M2B_LED: nets M2B_LED P3V3_M2B_L PU_M2B_CLKREQ_N
net group M2C_LED: nets M2C_LED P3V3_M2C_L PU_M2C_CLKREQ_N
net group M2D_LED: nets M2D_LED P3V3_M2D_L PU_M2D_CLKREQ_N
net group M2E_LED: nets M2E_LED P3V3_M2E_L PU_M2E_CLKREQ_N
net group M2F_LED: nets M2F_LED P3V3_M2F_L PU_M2F_CLKREQ_N
net group M2G_LED: nets M2G_LED P3V3_M2G_L PU_M2G_CLKREQ_N
net group M2I_LED: nets M2I_LED P3V3_M2I_L PU_M2I_CLKREQ_N
net group M2J_LED: nets M2J_LED P3V3_M2J_L PU_M2J_CLKREQ_N
net group M2K_LED: nets M2K_LED P3V3_M2K_L PU_M2K_CLKREQ_N
net group M2L_LED: nets M2L_LED P3V3_M2L_L PU_M2L_CLKREQ_N
net group P0V9_CTRL: nets FM_POWER_EN FM_POWER_EN_R FM_POWER_EN_R1 P0V9_CTRL P1V8_EN P3V3_STBY_TAKE1 P3V3_STBY_VCC P3V3_STBY_VDRV1 P3V3_STBY_VDRV2 PWRGD_P3V3_STBY
net group P3E_PESW_M2A_TX0_C_DN: nets P3E_PESW_M2A_TX0_C_DN
net group P3E_PESW_M2A_TX0_C_DP: nets P3E_PESW_M2A_TX0_C_DP
net group P3E_PESW_M2A_TX1_C_DN: nets P3E_PESW_M2A_TX1_C_DN
net group P3E_PESW_M2A_TX1_C_DP: nets P3E_PESW_M2A_TX1_C_DP
net group P3E_PESW_M2A_TX2_C_DN: nets P3E_PESW_M2A_TX2_C_DN
net group P3E_PESW_M2A_TX2_C_DP: nets P3E_PESW_M2A_TX2_C_DP
net group P3E_PESW_M2A_TX3_C_DN: nets P3E_PESW_M2A_TX3_C_DN
net group P3E_PESW_M2A_TX3_C_DP: nets P3E_PESW_M2A_TX3_C_DP
net group P3E_PESW_M2B_TX0_C_DN: nets P3E_PESW_M2B_TX0_C_DN
net group P3E_PESW_M2B_TX0_C_DP: nets P3E_PESW_M2B_TX0_C_DP
net group P3E_PESW_M2B_TX1_C_DN: nets P3E_PESW_M2B_TX1_C_DN
net group P3E_PESW_M2B_TX1_C_DP: nets P3E_PESW_M2B_TX1_C_DP
net group P3E_PESW_M2B_TX2_C_DN: nets P3E_PESW_M2B_TX2_C_DN
net group P3E_PESW_M2B_TX2_C_DP: nets P3E_PESW_M2B_TX2_C_DP
net group P3E_PESW_M2B_TX3_C_DN: nets P3E_PESW_M2B_TX3_C_DN
net group P3E_PESW_M2B_TX3_C_DP: nets P3E_PESW_M2B_TX3_C_DP
net group P3E_PESW_M2C_TX0_C_DN: nets P3E_PESW_M2C_TX0_C_DN
net group P3E_PESW_M2C_TX0_C_DP: nets P3E_PESW_M2C_TX0_C_DP
net group P3E_PESW_M2C_TX1_C_DN: nets P3E_PESW_M2C_TX1_C_DN
net group P3E_PESW_M2C_TX1_C_DP: nets P3E_PESW_M2C_TX1_C_DP
net group P3E_PESW_M2C_TX2_C_DN: nets P3E_PESW_M2C_TX2_C_DN
net group P3E_PESW_M2C_TX2_C_DP: nets P3E_PESW_M2C_TX2_C_DP
net group P3E_PESW_M2C_TX3_C_DN: nets P3E_PESW_M2C_TX3_C_DN
net group P3E_PESW_M2C_TX3_C_DP: nets P3E_PESW_M2C_TX3_C_DP
net group P3E_PESW_M2D_TX0_C_DN: nets P3E_PESW_M2D_TX0_C_DN
net group P3E_PESW_M2D_TX0_C_DP: nets P3E_PESW_M2D_TX0_C_DP
net group P3E_PESW_M2D_TX1_C_DN: nets P3E_PESW_M2D_TX1_C_DN
net group P3E_PESW_M2D_TX1_C_DP: nets P3E_PESW_M2D_TX1_C_DP
net group P3E_PESW_M2D_TX2_C_DN: nets P3E_PESW_M2D_TX2_C_DN
net group P3E_PESW_M2D_TX2_C_DP: nets P3E_PESW_M2D_TX2_C_DP
net group P3E_PESW_M2D_TX3_C_DN: nets P3E_PESW_M2D_TX3_C_DN
net group P3E_PESW_M2D_TX3_C_DP: nets P3E_PESW_M2D_TX3_C_DP
net group P3E_PESW_M2I_TX0_C_DN: nets P3E_PESW_M2I_TX0_C_DN
net group P3E_PESW_M2I_TX0_C_DP: nets P3E_PESW_M2I_TX0_C_DP
net group P3E_PESW_M2I_TX1_C_DN: nets P3E_PESW_M2I_TX1_C_DN
net group P3E_PESW_M2I_TX1_C_DP: nets P3E_PESW_M2I_TX1_C_DP
net group P3E_PESW_M2I_TX2_C_DN: nets P3E_PESW_M2I_TX2_C_DN
net group P3E_PESW_M2I_TX2_C_DP: nets P3E_PESW_M2I_TX2_C_DP
net group P3E_PESW_M2I_TX3_C_DN: nets P3E_PESW_M2I_TX3_C_DN
net group P3E_PESW_M2I_TX3_C_DP: nets P3E_PESW_M2I_TX3_C_DP
net group P3E_PESW_M2J_TX0_C_DN: nets P3E_PESW_M2J_TX0_C_DN
net group P3E_PESW_M2J_TX0_C_DP: nets P3E_PESW_M2J_TX0_C_DP
net group P3E_PESW_M2J_TX1_C_DN: nets P3E_PESW_M2J_TX1_C_DN
net group P3E_PESW_M2J_TX1_C_DP: nets P3E_PESW_M2J_TX1_C_DP
net group P3E_PESW_M2J_TX2_C_DN: nets P3E_PESW_M2J_TX2_C_DN
net group P3E_PESW_M2J_TX2_C_DP: nets P3E_PESW_M2J_TX2_C_DP
net group P3E_PESW_M2J_TX3_C_DN: nets P3E_PESW_M2J_TX3_C_DN
net group P3E_PESW_M2J_TX3_C_DP: nets P3E_PESW_M2J_TX3_C_DP
net group P3V3_M2H_L: nets M2H_LED P3V3_M2H_L PU_M2H_CLKREQ_N
net group P3V3_STBY_VOSNS+: nets N13628460 P3V3_STBY_VOSNS+ P3V3_STBY_VOSNS-
net group RESET: nets FM_OE_RST_N P3V3_STBY_PS#1 P3V3_STBY_PS#2 PWRGD_CLK_ZL30281 PWRGD_GPV2_SYS PWRGD_P0V92 PWRGD_P1V8 RST_PE_MOS_G
net group RST_PE_BUF_N_R2: nets RST_PE_BUF_N_R2 RST_PE_MOS_N_R2 RST_PE_N RST_PE_N_R1 RST_PE_PESW_GPIO15_N RST_PE_PESW_GPIO28_N RST_PE_PESW_GPIO29_N RST_PE_PESW_GPIO30_N RST_PE_PESW_GPIO31_N RST_PE_PESW_GPIO35_N RST_PE_PESW_GPIO_N_R
net group SMB: nets SMB_M2A_ALERT_N SMB_M2B_ALERT_N SMB_M2C_ALERT_N SMB_M2D_ALERT_N SMB_M2E_ALERT_N SMB_M2F_ALERT_N SMB_M2G_ALERT_N SMB_M2H_ALERT_N SMB_M2I_ALERT_N SMB_M2J_ALERT_N SMB_M2K_ALERT_N SMB_M2L_ALERT_N
net group SMB_BIC_CPLD_0_CLK: nets SMB_BIC_CPLD_0_CLK SMB_BIC_CPLD_0_CLK_R1 SMB_BIC_CPLD_0_CLK_R2
net group SMB_BIC_CPLD_0_DAT: nets SMB_BIC_CPLD_0_DAT SMB_BIC_CPLD_0_DAT_R1 SMB_BIC_CPLD_0_DAT_R2
net group SMB_BIC_CPLD_1_CLK: nets SMB_BIC_CPLD_1_CLK SMB_BIC_CPLD_1_CLK_R1 SMB_BIC_CPLD_1_CLK_R2
net group SMB_BIC_CPLD_1_DAT: nets SMB_BIC_CPLD_1_DAT SMB_BIC_CPLD_1_DAT_R1 SMB_BIC_CPLD_1_DAT_R2
net group SMB_BIC_VR_CLK: nets SMB_BIC_VR_CLK SMB_BIC_VR_CLK_R1 SMB_BIC_VR_CLK_R2
net group SMB_BIC_VR_DAT: nets SMB_BIC_VR_DAT SMB_BIC_VR_DAT_R1 SMB_BIC_VR_DAT_R2
net group SMB_BMC_3V3SB_CLK: nets SMB_BMC_3V3SB_CLK SMB_BMC_3V3SB_CLK_R1 SMB_BMC_3V3SB_CLK_R2
net group SMB_BMC_3V3SB_DAT: nets SMB_BMC_3V3SB_DAT SMB_BMC_3V3SB_DAT_R1 SMB_BMC_3V3SB_DAT_R2
net group SMB_M2A_INA231_CLK_R1: nets SMB_M2A_INA231_CLK_R1 SMB_M2A_P1V8_CLK SMB_M2A_P1V8_CLK_R2
net group SMB_M2A_INA231_DAT_R1: nets SMB_M2A_INA231_DAT_R1 SMB_M2A_P1V8_DAT SMB_M2A_P1V8_DAT_R2
net group SMB_M2AB_3V3SB_CLK: nets SMB_M2AB_3V3SB_CLK SMB_M2AB_3V3SB_CLK_R1 SMB_M2AB_3V3SB_CLK_R2
net group SMB_M2AB_3V3SB_DAT: nets SMB_M2AB_3V3SB_DAT SMB_M2AB_3V3SB_DAT_R1 SMB_M2AB_3V3SB_DAT_R2
net group SMB_M2B_INA231_CLK_R1: nets SMB_M2B_INA231_CLK_R1 SMB_M2B_P1V8_CLK SMB_M2B_P1V8_CLK_R2
net group SMB_M2B_INA231_DAT_R1: nets SMB_M2B_INA231_DAT_R1 SMB_M2B_P1V8_DAT SMB_M2B_P1V8_DAT_R2
net group SMB_M2C_INA231_CLK_R1: nets SMB_M2C_INA231_CLK_R1 SMB_M2C_P1V8_CLK SMB_M2C_P1V8_CLK_R2
net group SMB_M2C_INA231_DAT_R1: nets SMB_M2C_INA231_DAT_R1 SMB_M2C_P1V8_DAT SMB_M2C_P1V8_DAT_R2
net group SMB_M2CD_3V3SB_CLK: nets SMB_M2CD_3V3SB_CLK SMB_M2CD_3V3SB_CLK_R1 SMB_M2CD_3V3SB_CLK_R2
net group SMB_M2CD_3V3SB_DAT: nets SMB_M2CD_3V3SB_DAT SMB_M2CD_3V3SB_DAT_R1 SMB_M2CD_3V3SB_DAT_R2
net group SMB_M2D_INA231_CLK_R1: nets SMB_M2D_INA231_CLK_R1 SMB_M2D_P1V8_CLK SMB_M2D_P1V8_CLK_R2
net group SMB_M2D_INA231_DAT_R1: nets SMB_M2D_INA231_DAT_R1 SMB_M2D_P1V8_DAT SMB_M2D_P1V8_DAT_R2
net group SMB_M2E_INA231_CLK_R1: nets SMB_M2E_INA231_CLK_R1 SMB_M2E_P1V8_CLK SMB_M2E_P1V8_CLK_R2
net group SMB_M2E_INA231_DAT_R1: nets SMB_M2E_INA231_DAT_R1 SMB_M2E_P1V8_DAT SMB_M2E_P1V8_DAT_R2
net group SMB_M2EF_3V3SB_CLK: nets SMB_M2EF_3V3SB_CLK SMB_M2EF_3V3SB_CLK_R1 SMB_M2EF_3V3SB_CLK_R2
net group SMB_M2EF_3V3SB_DAT: nets SMB_M2EF_3V3SB_DAT SMB_M2EF_3V3SB_DAT_R1 SMB_M2EF_3V3SB_DAT_R2
net group SMB_M2F_INA231_CLK_R1: nets SMB_M2F_INA231_CLK_R1 SMB_M2F_P1V8_CLK SMB_M2F_P1V8_CLK_R2
net group SMB_M2F_INA231_DAT_R1: nets SMB_M2F_INA231_DAT_R1 SMB_M2F_P1V8_DAT SMB_M2F_P1V8_DAT_R2
net group SMB_M2G_INA231_CLK_R1: nets SMB_M2G_INA231_CLK_R1 SMB_M2G_P1V8_CLK SMB_M2G_P1V8_CLK_R2
net group SMB_M2G_INA231_DAT_R1: nets SMB_M2G_INA231_DAT_R1 SMB_M2G_P1V8_DAT SMB_M2G_P1V8_DAT_R2
net group SMB_M2GH_3V3SB_CLK: nets SMB_M2GH_3V3SB_CLK SMB_M2GH_3V3SB_CLK_R1 SMB_M2GH_3V3SB_CLK_R2
net group SMB_M2GH_3V3SB_DAT: nets SMB_M2GH_3V3SB_DAT SMB_M2GH_3V3SB_DAT_R1 SMB_M2GH_3V3SB_DAT_R2
net group SMB_M2H_INA231_CLK_R1: nets SMB_M2H_INA231_CLK_R1 SMB_M2H_P1V8_CLK SMB_M2H_P1V8_CLK_R2
net group SMB_M2H_INA231_DAT_R1: nets SMB_M2H_INA231_DAT_R1 SMB_M2H_P1V8_DAT SMB_M2H_P1V8_DAT_R2
net group SMB_M2I_INA231_CLK_R1: nets SMB_M2I_INA231_CLK_R1 SMB_M2I_P1V8_CLK SMB_M2I_P1V8_CLK_R2
net group SMB_M2I_INA231_DAT_R1: nets SMB_M2I_INA231_DAT_R1 SMB_M2I_P1V8_DAT SMB_M2I_P1V8_DAT_R2
net group SMB_M2IJ_3V3SB_CLK: nets SMB_M2IJ_3V3SB_CLK SMB_M2IJ_3V3SB_CLK_R1 SMB_M2IJ_3V3SB_CLK_R2
net group SMB_M2IJ_3V3SB_DAT: nets SMB_M2IJ_3V3SB_DAT SMB_M2IJ_3V3SB_DAT_R1 SMB_M2IJ_3V3SB_DAT_R2
net group SMB_M2J_INA231_CLK_R1: nets SMB_M2J_INA231_CLK_R1 SMB_M2J_P1V8_CLK SMB_M2J_P1V8_CLK_R2
net group SMB_M2J_INA231_DAT_R1: nets SMB_M2J_INA231_DAT_R1 SMB_M2J_P1V8_DAT SMB_M2J_P1V8_DAT_R2
net group SMB_M2K_INA231_CLK_R1: nets SMB_M2K_INA231_CLK_R1 SMB_M2K_P1V8_CLK SMB_M2K_P1V8_CLK_R2
net group SMB_M2K_INA231_DAT_R1: nets SMB_M2K_INA231_DAT_R1 SMB_M2K_P1V8_DAT SMB_M2K_P1V8_DAT_R2
net group SMB_M2KL_3V3SB_CLK: nets SMB_M2KL_3V3SB_CLK SMB_M2KL_3V3SB_CLK_R1 SMB_M2KL_3V3SB_CLK_R2
net group SMB_M2KL_3V3SB_DAT: nets SMB_M2KL_3V3SB_DAT SMB_M2KL_3V3SB_DAT_R1 SMB_M2KL_3V3SB_DAT_R2
net group SMB_M2L_INA231_CLK_R1: nets SMB_M2L_INA231_CLK_R1 SMB_M2L_P1V8_CLK SMB_M2L_P1V8_CLK_R2
net group SMB_M2L_INA231_DAT_R1: nets SMB_M2L_INA231_DAT_R1 SMB_M2L_P1V8_DAT SMB_M2L_P1V8_DAT_R2
net group SMB_PESW_3V3SB_CLK: nets SMB_PESW_3V3SB_CLK SMB_PESW_3V3SB_CLK_R1 SMB_PESW_3V3SB_CLK_R2
net group SMB_PESW_3V3SB_DAT: nets SMB_PESW_3V3SB_DAT SMB_PESW_3V3SB_DAT_R1 SMB_PESW_3V3SB_DAT_R2
net group SMB_PESW_P1V8_CLK: nets SMB_PESW_P1V8_CLK SMB_PESW_P1V8_CLK_R1 SMB_PESW_P1V8_CLK_R2
net group SMB_PESW_P1V8_DAT: nets SMB_PESW_P1V8_DAT SMB_PESW_P1V8_DAT_R1 SMB_PESW_P1V8_DAT_R2
net group SMB_SENSOR_3V3SB_DAT: nets SMB_SENSOR_3V3SB_DAT SMB_SENSOR_3V3SB_DAT_R1 SMB_SENSOR_3V3SB_DAT_R2 SMB_SENSOR_3V3SB_DAT_R3 SMB_SENSOR_DB1200_DAT_R1 SMB_SENSOR_FRU_DAT_R1 SMB_SENSOR_I2C_GPIO_DAT_R1 SMB_SENSOR_INA230_DAT_R1 SMB_SENSOR_TMP75_DAT_0_R1 SMB_SENSOR_TMP75_DAT_1_R1
net group SMB_SENSOR_DB1200_CLK_R1: nets SMB_SENSOR_3V3SB_CLK SMB_SENSOR_3V3SB_CLK_R1 SMB_SENSOR_3V3SB_CLK_R2 SMB_SENSOR_3V3SB_CLK_R3 SMB_SENSOR_DB1200_CLK_R1 SMB_SENSOR_FRU_CLK_R1 SMB_SENSOR_I2C_GPIO_CLK_R1 SMB_SENSOR_INA230_CLK_R1 SMB_SENSOR_TMP75_CLK_0_R1 SMB_SENSOR_TMP75_CLK_1_R1
net group SPI_PESW_FLASH_CLK: nets SPI_PESW_FLASH_CLK
net group SPI_PESW_FLASH_CSB_0: nets SPI_PESW_FLASH_CSB_0
net group SPI_PESW_FLASH_DAT_0: nets SPI_PESW_FLASH_DAT_0
net group SPI_PESW_FLASH_DAT_1_R2: nets SPI_PESW_FLASH_DAT_1 SPI_PESW_FLASH_DAT_1_R1 SPI_PESW_FLASH_DAT_1_R2
net group SPI_PESW_FLASH_DAT_2_R2: nets SPI_PESW_FLASH_DAT_2 SPI_PESW_FLASH_DAT_2_R1 SPI_PESW_FLASH_DAT_2_R2
net group UART: nets COM_GP_RX UART_PESW_USIN UART_PESW_USOUT
net group UART_BIC_TXD: nets UART_BIC_TXD
net group UART_PESW_CPLD_USIN: nets UART_PESW_CPLD_USIN UART_PESW_CPLD_USIN_R UART_PESW_USIN_3V3SB UART_PESW_USIN_3V3SB_R
net group UART_PESW_CPLD_USOUT: nets UART_PESW_CPLD_USOUT UART_PESW_CPLD_USOUT_R UART_PESW_USOUT_3V3SB UART_PESW_USOUT_3V3SB_R
net group VSENSE_P12V_INA230_INN: nets VSENSE_P12V_INA230_INN VSENSE_P12V_INA230_INP VSENSE_P12V_INA230_R_INN VSENSE_P12V_INA230_R_INP

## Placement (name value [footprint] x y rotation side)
C1  100NF  [C0402]  99.31 32.86 270 bottom
C2  100NF  [C0402]  97.36 33.3 0 bottom
C6  100NF  [C0402]  43.34 122.5 180 top
C9  100NF  [C0402]  48.02 123.53 0 top
C12  100NF  [C0402]  19.24 123.52 180 top
C15  100NF  [C0402]  38.01 122.33 0 top
C18  100NF  [C0402]  43.04 130.75 180 bottom
C21  100NF  [C0402]  49.96 131.59 0 bottom
C24  100NF  [C0402]  71.82 130.76 0 bottom
C27  100NF  [C0402]  67.07 130.74 180 bottom
C30  100NF  [C0402]  144.03 129.66 0 bottom
C33  100NF  [C0402]  124.83 129.75 180 bottom
C36  100NF  [C0402]  163.05 126.29 180 bottom
C39  100NF  [C0402]  168.08 125.35 0 bottom
C44  100NF  [C0402]  12.29 37.13 270 top
C45  100NF  [C0402]  16.29 78.68 90 bottom
C46  100NF  [C0402]  161.16 51.61 270 bottom
C49  1UF  [C0402]  24.28 111.15 270 top
C70  100NF  [C0402]  45.39 66.7 180 bottom
C87  100NF  [C0402]  48.02 122.51 0 top
C89  100NF  [C0402]  24.35 123.51 0 top
C92  100NF  [C0402]  43.08 124.76 180 bottom
C94  100NF  [C0402]  52.19 130.5 180 bottom
C97  100NF  [C0402]  139.05 130.76 180 bottom
C100  100NF  [C0402]  148.42 128.5 180 bottom
C103  100NF  [C0402]  45.31 71.5 180 bottom
C104  100NF  [C0402]  24.07 120.02 180 bottom
C121  100NF  [C0402]  15.77 81.33 270 top
C122  100NF  [C0402]  13.08 108.94 90 top
C123  100NF  [C0402]  44.63 118.2 180 top
C125  1UF  [C0402]  49.51 110.9 270 top
C126  100NF  [C0402]  69.94 117.21 180 top
C128  1UF  [C0402]  73.36 110.81 180 top
C129  100NF  [C0402]  94.71 117.65 180 top
C131  1UF  [C0402]  99.37 110.68 270 top
C132  100NF  [C0402]  118.14 118.42 180 top
C134  1UF  [C0402]  123.43 111 270 top
C135  100NF  [C0402]  142.3 117.75 180 top
C137  1UF  [C0402]  148.77 111.88 270 top
C140  100NF  [C0402]  20.13 116.27 180 top
C141  100NF  [C0402]  44.63 116.13 180 top
C142  100NF  [C0402]  69.22 113.97 180 top
C143  100NF  [C0402]  94.73 114.79 180 top
C144  100NF  [C0402]  118.52 115.7 180 top
C145  100NF  [C0402]  150.64 117.41 180 top
C146  10UF  [C0603]  19.69 115.04 180 top
C147  10UF  [C0603]  44.73 114.94 180 top
C148  10UF  [C0603]  69.32 112.74 180 top
C149  10UF  [C0603]  94.73 113.57 180 top
C150  10UF  [C0603]  118.52 114.44 180 top
C151  10UF  [C0603]  144.04 115.32 180 top
C152  1UF  [C0402]  61.91 122.3 0 top
C153  10UF  [C0603]  61.91 121.08 0 top
C154  1UF  [C0402]  61.91 123.37 0 top
C155  10UF  [C0603]  47.92 121.26 0 top
C156  1UF  [C0402]  43.34 123.52 180 top
C157  10UF  [C0603]  43.32 121.26 180 top
C158  1UF  [C0402]  19.24 122.5 180 top
C159  10UF  [C0603]  19.06 121.26 180 top
C160  1UF  [C0402]  24.35 122.5 0 top
C161  10UF  [C0603]  23.92 121.26 0 top
C162  1UF  [C0402]  38.01 123.39 0 top
C163  10UF  [C0603]  37.91 121.08 0 top
C164  1UF  [C0402]  28.4 130.68 180 bottom
C165  10UF  [C0603]  47.85 123.28 0 bottom
C166  1UF  [C0402]  28.4 129.67 180 bottom
C167  10UF  [C0603]  28.45 128.47 180 bottom
C168  1UF  [C0402]  49.98 130.56 0 bottom
C169  10UF  [C0603]  47.85 124.78 0 bottom
C170  1UF  [C0402]  71.8 128.99 0 bottom
C171  10UF  [C0603]  72.06 126.32 0 bottom
C172  1UF  [C0402]  51.86 128.04 180 bottom
C173  10UF  [C0603]  52.15 126.26 180 bottom
C174  1UF  [C0402]  67.08 125.52 180 bottom
C175  10UF  [C0603]  71.91 121.26 0 bottom
C176  1UF  [C0402]  144.12 123.52 0 bottom
C177  10UF  [C0603]  144.08 125.35 0 bottom
C178  1UF  [C0402]  139.06 125.37 180 bottom
C179  10UF  [C0603]  143.92 121.26 0 bottom
C180  1UF  [C0402]  124.83 130.76 180 bottom
C181  10UF  [C0603]  124.5 128.55 180 bottom
C182  1UF  [C0402]  148.88 130.76 180 bottom
C183  10UF  [C0603]  148.5 126.4 180 bottom
C184  1UF  [C0402]  163.05 130.76 180 bottom
C185  10UF  [C0603]  168.39 126.7 0 bottom
C186  1UF  [C0402]  168.15 129.22 0 bottom
C187  10UF  [C0603]  168.13 123.52 0 bottom
C188  22UF  [C0805_H61]  19.71 113.34 180 top
C189  22UF  [C0805_H61]  44.76 113.28 180 top
C190  22UF  [C0805_H61]  69.86 110.91 180 top
C191  22UF  [C0805_H61]  94.84 111.81 180 top
C192  22UF  [C0805_H61]  118.73 112.74 180 top
C193  22UF  [C0805_H61]  144.3 113.67 180 top
C197  100NF  [C0402]  96.03 130.29 0 bottom
C198  1UF  [C0402]  91.05 130.76 180 bottom
C199  10UF  [C0603]  75.99 126.01 180 bottom
C200  1UF  [C0402]  76.8 130.76 180 bottom
C201  10UF  [C0603]  96.39 126.55 0 bottom
C202  1UF  [C0402]  91.08 125.4 180 bottom
C203  10UF  [C0603]  95.92 121.26 0 bottom
C204  100NF  [C0402]  96.12 127.82 0 bottom
C205  100NF  [C0402]  76.81 129.75 180 bottom
C206  100NF  [C0402]  119.91 123.57 0 bottom
C207  1UF  [C0402]  100.8 128.95 180 bottom
C208  10UF  [C0603]  119.92 121.26 0 bottom
C209  1UF  [C0402]  100.79 130.53 180 bottom
C210  10UF  [C0603]  100.27 126.15 180 bottom
C211  1UF  [C0402]  119.8 129.3 0 bottom
C212  10UF  [C0603]  119.9 125.64 0 bottom
C213  100NF  [C0402]  115.05 130.76 180 bottom
C214  100NF  [C0402]  115.09 125.58 180 bottom
C215  100NF  [C0402]  96.02 123.52 0 top
C216  1UF  [C0402]  96.02 122.5 0 top
C217  10UF  [C0603]  91.32 121.23 180 top
C218  1UF  [C0402]  91.29 122.5 180 top
C219  10UF  [C0603]  95.92 121.26 0 top
C220  1UF  [C0402]  109.91 122.3 0 top
C221  10UF  [C0603]  109.91 121.08 0 top
C222  100NF  [C0402]  109.91 123.37 0 top
C223  100NF  [C0402]  91.29 123.52 180 top
C224  100NF  [C0402]  67.34 123.52 180 top
C225  1UF  [C0402]  86.01 122.33 0 top
C226  10UF  [C0603]  71.92 121.26 0 top
C227  1UF  [C0402]  67.34 122.5 180 top
C228  10UF  [C0603]  67.01 121.26 180 top
C229  1UF  [C0402]  86.01 123.39 0 top
C230  10UF  [C0603]  85.91 121.08 0 top
C231  100NF  [C0402]  72.02 122.5 0 top
C232  100NF  [C0402]  72.02 123.52 0 top
C233  100NF  [C0402]  143.92 123.52 0 top
C234  1UF  [C0402]  157.91 122.3 0 top
C235  10UF  [C0603]  139.14 121.26 180 top
C236  1UF  [C0402]  157.91 123.37 0 top
C237  10UF  [C0603]  157.91 121.08 0 top
C238  1UF  [C0402]  139.28 123.51 180 top
C239  10UF  [C0603]  143.92 121.26 0 top
C240  100NF  [C0402]  143.92 122.5 0 top
C241  100NF  [C0402]  139.28 122.49 180 top
C242  100NF  [C0402]  133.99 123.52 0 top
C243  1UF  [C0402]  115.24 123.52 180 top
C244  10UF  [C0603]  133.91 121.26 0 top
C245  1UF  [C0402]  119.89 122.5 0 top
C246  10UF  [C0603]  115.24 121.28 180 top
C247  1UF  [C0402]  115.24 122.5 180 top
C248  10UF  [C0603]  119.92 121.26 0 top
C249  100NF  [C0402]  133.99 122.5 0 top
C250  100NF  [C0402]  119.89 123.52 0 top
C251  10UF  [C0603]  65.81 112.61 0 bottom
C252  22UF  [C0805_H61]  42.57 113.63 0 bottom
C253  22UF  [C0805_H61]  66.08 108.85 0 bottom
C254  22UF  [C0805_H61]  90.8 111.83 0 bottom
C255  22UF  [C0805_H61]  115.2 111.07 0 bottom
C256  22UF  [C0805_H61]  140.34 112.52 0 bottom
C257  22UF  [C0805_H61]  167.54 115.27 0 bottom
C258  100NF  [C0402]  42.57 116.91 0 bottom
C259  100NF  [C0402]  167.09 118.17 0 bottom
C260  100NF  [C0402]  90.8 114.75 0 bottom
C261  100NF  [C0402]  140.52 115.36 0 bottom
C262  100NF  [C0402]  65.71 113.99 0 bottom
C263  100NF  [C0402]  115.17 114.08 0 bottom
C264  10UF  [C0603]  42.75 115.54 0 bottom
C265  10UF  [C0603]  90.93 113.49 0 bottom
C266  100NF  [C0402]  42.74 120.02 0 bottom
C267  1UF  [C0402]  38.66 113.13 0 bottom
C268  10UF  [C0603]  115.16 112.79 0 bottom
C269  100NF  [C0402]  66.66 117.28 0 bottom
C270  1UF  [C0402]  61.45 110.54 0 bottom
C271  100NF  [C0402]  90.09 118.05 0 bottom
C272  10UF  [C0603]  140.37 114.15 0 bottom
C273  1UF  [C0402]  85.48 110.25 270 bottom
C274  100NF  [C0402]  115.75 117.66 0 bottom
C275  1UF  [C0402]  110.66 110.45 270 bottom
C276  100NF  [C0402]  139.32 118.58 0 bottom
C277  1UF  [C0402]  134.75 110.91 270 bottom
C278  10UF  [C0603]  167.53 116.95 0 bottom
C279  100NF  [C0402]  167.1 121.31 0 bottom
C280  1UF  [C0402]  162.65 113.42 270 bottom
C377  0.22UF  [C0402]  188.3 58.73 180 bottom
C378  0.22UF  [C0402]  188.3 59.75 180 bottom
C379  0.22UF  [C0402]  190.3 57.22 180 bottom
C380  0.22UF  [C0402]  190.3 58.24 180 bottom
C381  0.22UF  [C0402]  193.2 55.91 180 bottom
C382  0.22UF  [C0402]  193.2 56.93 180 bottom
C383  0.22UF  [C0402]  187.08 57.37 270 top
C384  0.22UF  [C0402]  188.1 57.37 270 top
C385  0.22UF  [C0402]  189.38 57.37 270 top
C386  0.22UF  [C0402]  190.39 57.37 270 top
C387  0.22UF  [C0402]  191.83 57.35 270 top
C388  0.22UF  [C0402]  192.84 57.35 270 top
C389  0.22UF  [C0402]  194.23 57.35 270 top
C390  0.22UF  [C0402]  195.25 57.35 270 top
C391  0.22UF  [C0402]  197.54 57.31 270 top
C392  0.22UF  [C0402]  196.53 57.31 270 top
C393  0.22UF  [C0402]  199.88 57.29 270 top
C394  0.22UF  [C0402]  198.87 57.29 270 top
C395  0.22UF  [C0402]  202.27 57.29 270 top
C396  0.22UF  [C0402]  201.25 57.29 270 top
C397  0.22UF  [C0402]  204.63 57.31 270 top
C398  0.22UF  [C0402]  203.62 57.31 270 top
C399  0.22UF  [C0402]  198.86 59.07 270 bottom
C400  0.22UF  [C0402]  197.84 59.07 270 bottom
C401  0.22UF  [C0402]  201.56 59.07 270 bottom
C402  0.22UF  [C0402]  200.55 59.07 270 bottom
C403  0.22UF  [C0402]  203.76 63.89 270 bottom
C404  0.22UF  [C0402]  202.75 63.89 270 bottom
C405  0.22UF  [C0402]  205.35 65.85 270 bottom
C406  0.22UF  [C0402]  204.33 65.85 270 bottom
C407  0.22UF  [C0402]  186.31 60.22 180 bottom
C408  0.22UF  [C0402]  186.31 61.24 180 bottom
C409  0.22UF  [C0402]  151.68 97.71 180 top
C410  0.22UF  [C0402]  151.68 96.7 180 top
C411  0.22UF  [C0402]  153.51 96.35 180 top
C412  0.22UF  [C0402]  153.51 95.33 180 top
C413  0.22UF  [C0402]  151.68 95.01 180 top
C414  0.22UF  [C0402]  151.68 93.99 180 top
C415  0.22UF  [C0402]  153.51 93.65 180 top
C416  0.22UF  [C0402]  153.51 92.63 180 top
C417  0.22UF  [C0402]  151.68 92.31 180 top
C418  0.22UF  [C0402]  151.68 91.29 180 top
C419  0.22UF  [C0402]  153.51 90.94 180 top
C420  0.22UF  [C0402]  153.51 89.93 180 top
C421  0.22UF  [C0402]  151.68 89.6 180 top
C422  0.22UF  [C0402]  151.68 88.59 180 top
C423  0.22UF  [C0402]  153.51 88.24 180 top
C424  0.22UF  [C0402]  153.51 87.22 180 top
C425  0.22UF  [C0402]  151.68 86.9 180 top
C426  0.22UF  [C0402]  151.68 85.88 180 top
C427  0.22UF  [C0402]  153.51 85.54 180 top
C428  0.22UF  [C0402]  153.51 84.52 180 top
C429  0.22UF  [C0402]  151.68 84.2 180 top
C430  0.22UF  [C0402]  151.68 83.18 180 top
C431  0.22UF  [C0402]  153.51 82.83 180 top
C432  0.22UF  [C0402]  153.51 81.82 180 top
C433  0.22UF  [C0402]  151.68 81.49 180 top
C434  0.22UF  [C0402]  151.68 80.48 180 top
C435  0.22UF  [C0402]  153.51 80.13 180 top
C436  0.22UF  [C0402]  153.51 79.12 180 top
C437  0.22UF  [C0402]  151.68 78.79 180 top
C438  0.22UF  [C0402]  151.68 77.77 180 top
C439  0.22UF  [C0402]  153.51 99.05 180 top
C440  0.22UF  [C0402]  153.51 98.04 180 top
C537  0.1UF  [C0201]  183.65 82.43 0 bottom
C538  0.1UF  [C0201]  187.58 81.08 270 bottom
C539  0.1UF  [C0201]  179.59 85.56 0 bottom
C540  0.1UF  [C0201]  188.47 85.63 180 bottom
C541  0.1UF  [C0201]  185.55 81.08 270 bottom
C542  0.1UF  [C0201]  183.65 85.47 0 bottom
C543  0.1UF  [C0201]  186.59 81.08 90 bottom
C545  0.1UF  [C0201]  176.45 85.39 180 bottom
C546  0.1UF  [C0201]  176.48 86.66 180 bottom
C547  0.1UF  [C0201]  178.59 84.56 0 bottom
C548  0.1UF  [C0201]  183.65 81.41 0 bottom
C549  0.1UF  [C0201]  183.64 73.35 0 bottom
C550  0.1UF  [C0201]  179.53 78.74 180 bottom
C551  0.1UF  [C0201]  181.57 76.71 180 bottom
C552  0.1UF  [C0201]  189.61 74.32 0 bottom
C553  0.1UF  [C0201]  185.59 75.56 0 bottom
C554  0.1UF  [C0201]  187.59 77.56 0 bottom
C555  0.1UF  [C0201]  183.63 86.45 180 bottom
C556  0.1UF  [C0201]  189.79 82.65 0 bottom
C557  0.1UF  [C0201]  179.53 73.41 180 bottom
C558  0.1UF  [C0201]  183.65 74.34 180 bottom
C559  0.1UF  [C0201]  186.61 86.33 0 bottom
C560  0.1UF  [C0201]  185.59 74.48 0 bottom
C561  0.1UF  [C0201]  183.65 75.33 0 bottom
C562  0.1UF  [C0201]  187.59 75.56 0 bottom
C563  0.1UF  [C0201]  181.57 78.74 180 bottom
C564  0.1UF  [C0201]  177.5 76.71 180 bottom
C565  0.1UF  [C0201]  179.53 76.71 180 bottom
C566  0.1UF  [C0201]  177.5 74.93 180 bottom
C567  0.1UF  [C0201]  179.53 74.68 180 bottom
C568  0.1UF  [C0201]  181.57 74.68 180 bottom
C569  0.1UF  [C0201]  185.62 78.23 180 bottom
C570  0.1UF  [C0201]  186.54 84.43 180 bottom
C571  0.1UF  [C0201]  183.65 76.33 180 bottom
C572  0.1UF  [C0201]  183.65 77.35 0 bottom
C573  0.1UF  [C0201]  183.65 78.36 180 bottom
C574  0.1UF  [C0201]  183.65 79.38 0 bottom
C575  0.1UF  [C0201]  183.65 80.39 180 bottom
C576  0.1UF  [C0201]  183.65 83.44 180 bottom
C577  0.1UF  [C0201]  183.64 84.46 180 bottom
C578  0.1UF  [C0201]  181.59 84.48 0 bottom
C579  0.1UF  [C0201]  178.59 82.56 0 bottom
C580  10UF  [C0402]  182.07 81.03 270 bottom
C581  10UF  [C0402]  181.06 81.03 90 bottom
C582  10UF  [C0402]  180.04 81.03 270 bottom
C583  10UF  [C0402]  179.03 81.03 90 bottom
